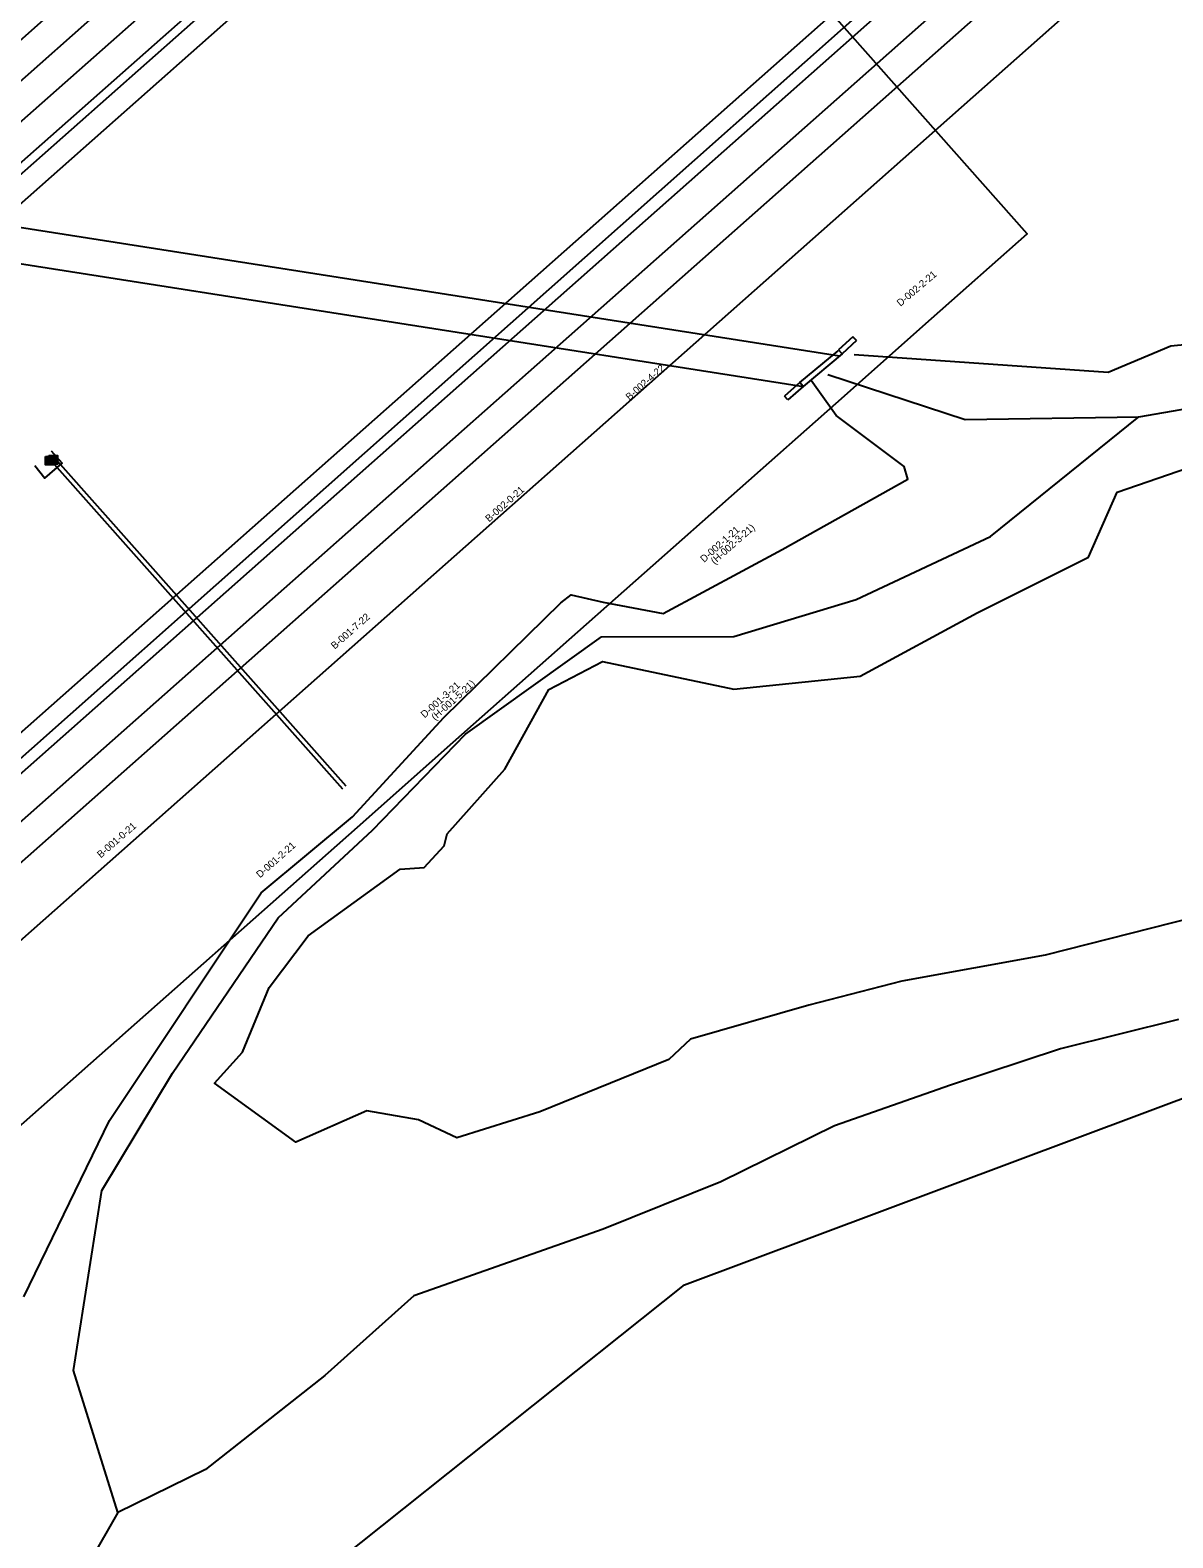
# Model space of a CAD drawing. Extents: x 2265470 to 2269397, y 712607 to 716300.
# Drawn here: x 2267795 to 2268242, y 714269 to 714859 of the extents above; entities that cross this region are included whole.
import ezdxf

# ---------------------------------------------------------------- set-up
doc = ezdxf.new("R2010")
doc.units = 0
for name, color, linetype in [('BD_P_Text', 7, 'Continuous'), ('BR_X_SV_Abut_Text', 7, 'Continuous'), ('DR_X_Culvert', 7, 'Continuous'), ('GE_X_Alignment', 7, 'Continuous'), ('GT_Project_Soil_Boring', 7, 'Continuous'), ('GT_Project_Text', 7, 'Continuous'), ('PV_X_Shoulder_Rumble_Strip', 7, 'Continuous'), ('SC_Scratch1', 7, 'Continuous'), ('SC_Scratch9', 7, 'Continuous'), ('SV_Crossing', 7, 'Continuous'), ('SV_X_Mon_Cells_Found', 7, 'Continuous'), ('SV_X_Top_of_Bank', 7, 'Continuous'), ('TX_X_20', 7, 'Continuous')]:
    doc.layers.add(name, color=color, linetype=linetype)

msp = doc.modelspace()

# ---------------------------------------------------------------- linework, layer by layer
at = {"layer": 'BD_P_Text'}
for p, q in [((2265487.76, 712798.68), (2269337.69, 716208.98)), ((2265495.72, 712789.7), (2269345.65, 716200)), ((2265628.32, 712633.29), (2269392.86, 715967.96)), ((2265635.88, 712623.96), (2269394.26, 715953.16))]:
    msp.add_line(p, q, dxfattribs=at)
at = {"layer": 'BR_X_SV_Abut_Text'}
for points in [[(2268373.69, 714748.17), (2268241.06, 714735.13), (2268216.5, 714724.92), (2268117.11, 714731.83)], [(2267920.97, 714551.08), (2267956.7, 714589.89), (2268002.35, 714634.71), (2268006.46, 714637.87), (2268018.9, 714635.03), (2268042.38, 714630.6), (2268089, 714655.62), (2268138.17, 714683.14), (2268136.64, 714688.08), (2268110.07, 714708.08), (2268100.31, 714721.75)], [(2268249.9, 714511.64), (2268191.91, 714496.92), (2268135.76, 714486.72), (2268099.47, 714477.33), (2268053.17, 714464.04), (2268044.65, 714456.13), (2267994.13, 714435.6), (2267961.75, 714425.43), (2267946.69, 714432.48), (2267926.46, 714435.97), (2267898.73, 714423.75), (2267866.87, 714446.86), (2267877.9, 714458.89), (2267888.38, 714484.23), (2267903.62, 714504.52), (2267939.62, 714530.59), (2267948.92, 714531.18), (2267956.82, 714539.61), (2267957.98, 714544.33), (2267980.52, 714569.66), (2267997.74, 714600.86), (2268018.72, 714611.82), (2268070.13, 714601.01), (2268119.46, 714606.08), (2268165.21, 714630.83), (2268208.76, 714652.56), (2268220.07, 714678), (2268267.78, 714694.53)], [(2267547.6, 713612.15), (2267533.17, 713718.72), (2267570.3, 713837.81), (2267633.15, 713907.06), (2267732.69, 714003.58), (2267789.11, 714072.48), (2267915.9, 714260.4), (2268050.82, 714367.9), (2268281.68, 714454.38), (2268329.32, 714468.2), (2268437.4, 714511.98), (2268538.25, 714559.71), (2268592.99, 714593.43), (2268637.57, 714623.46), (2268704.3, 714621.21)], [(2267792.33, 714363.24), (2267825.85, 714432.22), (2267885.14, 714521.28), (2267920.97, 714551.08)]]:
    msp.add_lwpolyline(points, dxfattribs=at)
at = {"layer": 'DR_X_Culvert'}
for p, q in [((2267802.49, 714692.03), (2267802.49, 714692.03)), ((2267803.85, 714692.36), (2267803.85, 714692.36)), ((2267803.85, 714691.7), (2267803.85, 714691.7)), ((2267801.49, 714690.36), (2267801.49, 714690.36)), ((2267802.49, 714691.36), (2267802.49, 714691.36)), ((2267802.49, 714690.36), (2267802.49, 714690.36)), ((2267802.49, 714690.36), (2267802.49, 714690.36)), ((2267802.49, 714690.36), (2267802.49, 714690.36)), ((2267802.49, 714689.36), (2267802.49, 714689.36)), ((2267802.49, 714688.7), (2267802.49, 714688.7)), ((2267802.85, 714690.7), (2267802.85, 714690.7)), ((2267803.49, 714690.36), (2267803.49, 714690.36)), ((2267803.85, 714690.7), (2267803.85, 714690.7)), ((2267803.85, 714690.7), (2267803.85, 714690.7)), ((2267803.85, 714690.7), (2267803.85, 714690.7)), ((2267803.85, 714689.7), (2267803.85, 714689.7)), ((2267803.85, 714689.03), (2267803.85, 714689.03)), ((2267804.85, 714690.7), (2267804.85, 714690.7))]:
    msp.add_line(p, q, dxfattribs=at)
at = {"layer": 'GE_X_Alignment'}
for p, q in [((2265479.81, 712807.66), (2269338.54, 716225.76)), ((2265503.68, 712780.71), (2269349.21, 716187.12)), ((2265619.44, 712644.24), (2269391.23, 715985.32))]:
    msp.add_line(p, q, dxfattribs=at)
at = {"layer": 'GT_Project_Text'}
for p, q in [((2266703.72, 713827.7), (2269255.45, 716088.03)), ((2266674.89, 713595.2), (2269268.85, 715892.94)), ((2265650.54, 712606.64), (2269309.14, 715847.46))]:
    msp.add_line(p, q, dxfattribs=at)
at = {"layer": 'PV_X_Shoulder_Rumble_Strip'}
msp.add_lwpolyline([(2267796.61, 714688.46), (2267800.62, 714683.56), (2267807.36, 714689.42), (2267803.24, 714694.1)], dxfattribs=at)
at = {"layer": 'SC_Scratch1'}
for p, q in [((2266701.55, 713837.25), (2269251.37, 716095.9)), ((2266662.26, 713571.53), (2269272.16, 715889.2)), ((2267654.16, 714803.15), (2268111.44, 714731.41)), ((2267639.62, 714791.26), (2268097.26, 714719.47))]:
    msp.add_line(p, q, dxfattribs=at)
at = {"layer": 'SC_Scratch9'}
msp.add_lwpolyline([(2267507.89, 714713.84), (2267773.12, 714414.42), (2267847.98, 714480.73), (2267885.41, 714513.88), (2267922.83, 714547.03), (2267960.26, 714580.19), (2267997.69, 714613.34), (2268035.12, 714646.5), (2268072.54, 714679.65), (2268109.97, 714712.8), (2268147.4, 714745.96), (2268184.83, 714779.11), (2267919.6, 715078.53), (2267882.17, 715045.38), (2267844.74, 715012.22), (2267807.31, 714979.07), (2267769.89, 714945.92), (2267732.46, 714912.76), (2267695.03, 714879.61), (2267657.6, 714846.46), (2267620.18, 714813.3), (2267582.75, 714780.15)], close=True, dxfattribs=at)
at = {"layer": 'SV_Crossing'}
for p, q in [((2267804.2, 714689.06), (2267805.51, 714690.22)), ((2267804.2, 714689.06), (2267917.04, 714561.97)), ((2267805.51, 714690.22), (2267918.35, 714563.13))]:
    msp.add_line(p, q, dxfattribs=at)
at = {"layer": 'SV_X_Mon_Cells_Found'}
for p, q in [((2268160.53, 714706.43), (2268228.44, 714707.58)), ((2267829.06, 714278.8), (2267811.81, 714334.39))]:
    msp.add_line(p, q, dxfattribs=at)
for points in [[(2267811.81, 714334.39), (2267822.86, 714404.8), (2267850.44, 714450.72), (2267891.86, 714511.48), (2267928.78, 714545.76), (2267965.17, 714583.31), (2268018.32, 714621.47), (2268070.12, 714621.62), (2268117.91, 714636.1), (2268170.43, 714660.68), (2268228.44, 714707.58), (2268317.25, 714722.98), (2268375.02, 714728.24), (2268485.77, 714718.53), (2268537.5, 714714.72), (2268597.6, 714707.34), (2268714.12, 714666.42)], [(2268106.79, 714724.04), (2268160.53, 714706.43)], [(2268244.06, 714471.78), (2268197.91, 714460.22), (2268154.87, 714446.06), (2268109.39, 714430.08), (2268064.93, 714408.17), (2268018.92, 714389.72), (2267944.92, 714363.58), (2267910.08, 714332.4), (2267863.35, 714295.68), (2267829.06, 714278.8), (2267784.82, 714201.34), (2267746.13, 714126.36), (2267606.84, 713934.76), (2267529.49, 713864.11)]]:
    msp.add_lwpolyline(points, dxfattribs=at)
at = {"layer": 'SV_X_Top_of_Bank'}
for p, q in [((2267801.35, 714689.75), (2267803.1, 714691.51)), ((2267801.35, 714690.88), (2267801.97, 714691.51)), ((2267802.7, 714690.08), (2267804.46, 714691.84)), ((2267802.7, 714691.21), (2267803.33, 714691.84)), ((2267801.94, 714689.22), (2267803.64, 714690.91)), ((2267803.08, 714689.22), (2267803.64, 714689.78)), ((2267803.3, 714689.55), (2267804.99, 714691.24)), ((2267804.43, 714689.55), (2267804.99, 714690.11))]:
    msp.add_line(p, q, dxfattribs=at)
for points in [[(2267800.82, 714692.03), (2267804.16, 714692.03), (2267804.16, 714688.7), (2267800.82, 714688.7)], [(2267801.35, 714691.51), (2267803.64, 714691.51), (2267803.64, 714689.22), (2267801.35, 714689.22)], [(2267802.18, 714692.36), (2267805.51, 714692.36), (2267805.51, 714689.03), (2267802.18, 714689.03)], [(2267802.7, 714691.84), (2267804.99, 714691.84), (2267804.99, 714689.55), (2267802.7, 714689.55)], [(2267802.85, 714691.7), (2267804.85, 714691.7), (2267804.85, 714689.7), (2267802.85, 714689.7)], [(2267801.49, 714691.36), (2267803.49, 714691.36), (2267803.49, 714689.36), (2267801.49, 714689.36)]]:
    msp.add_lwpolyline(points, close=True, dxfattribs=at)
at = {"layer": 'TX_X_20'}
for p, q in [((2268116.68, 714738.89), (2268111.04, 714733.69)), ((2268118.03, 714737.41), (2268116.68, 714738.89)), ((2268095.93, 714720.96), (2268110.83, 714733.42)), ((2268112.39, 714732.22), (2268111.04, 714733.69)), ((2268118.03, 714737.41), (2268112.39, 714732.22)), ((2268112.39, 714732.22), (2268097.24, 714719.46)), ((2268095.93, 714720.96), (2268089.91, 714715.68)), ((2268097.24, 714719.46), (2268095.93, 714720.96)), ((2268091.23, 714714.18), (2268089.91, 714715.68)), ((2268097.24, 714719.46), (2268091.23, 714714.18))]:
    msp.add_line(p, q, dxfattribs=at)

# ---------------------------------------------------------------- texts
at = {"layer": 'GT_Project_Soil_Boring'}
for s, rotation, p in [('D-002-2-21', 40.35598, (2268135.25, 714750.57)), ('B-002-4-22', 41.31276, (2268029.27, 714713.81)), ('B-002-0-21', 41.53477, (2267974.36, 714666.18)), ('D-002-1-21', 41.53477, (2268058.43, 714650.38)), ('(H-002-3-21)', 41.53477, (2268062.55, 714649.62)), ('B-001-7-22', 41.53477, (2267913.98, 714616.44)), ('D-001-3-21', 41.53477, (2267949.1, 714589.53)), ('(H-001-5-21)', 41.53477, (2267953.2, 714588.6)), ('B-001-0-21', 41.01675, (2267822.48, 714534.74)), ('D-001-2-21', 41.53477, (2267884.75, 714526.91))]:
    msp.add_text(s, height=2.8, rotation=rotation, dxfattribs=at).set_placement(p)

doc.saveas('drawing.dxf')
